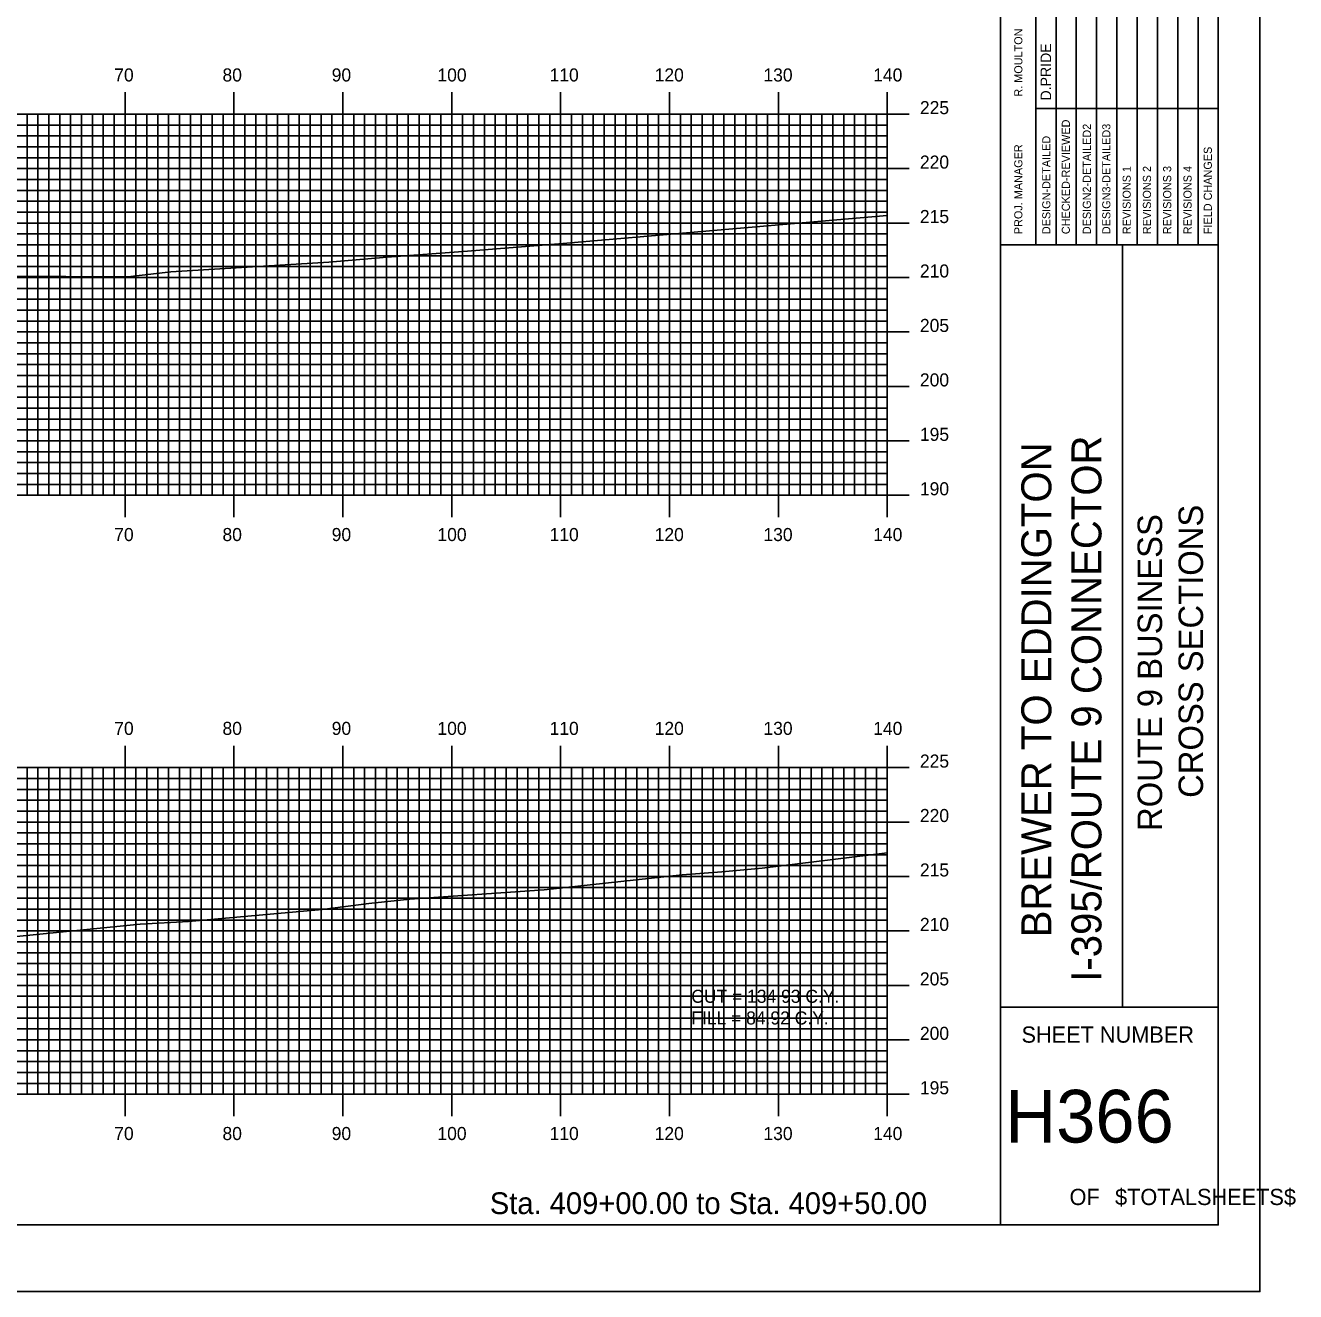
# Model space of a CAD drawing. Extents: x 852922 to 853266, y 364785 to 365005.
# Drawn here: x 853149.1 to 853265.7, y 364785.1 to 364901.4 of the extents above; entities that cross this region are included whole.
import ezdxf

# ---------------------------------------------------------------- set-up
doc = ezdxf.new("R2010")
doc.units = 0
for name, color, linetype in [('BORDER', 7, 'Continuous'), ('D_Text_Standard', 7, 'Continuous'), ('H_V ANNOTATION', 7, 'Continuous'), ('MAJOR', 7, 'Continuous'), ('MINOR', 7, 'Continuous'), ('PLOT BOUNDARY', 7, 'Continuous'), ('S_Roadway_Centerline', 7, 'Continuous')]:
    doc.layers.add(name, color=color, linetype=linetype)

msp = doc.modelspace()

# ---------------------------------------------------------------- linework, layer by layer
at = {"layer": 'BORDER'}
for p, q in [((853238.64, 364791.23), (853238.64, 365001.23)), ((853238.64, 364881.24), (853258.64, 364881.24)), ((853249.83, 364811.24), (853249.83, 364881.24)), ((853238.64, 364811.24), (853258.64, 364811.24))]:
    msp.add_line(p, q, dxfattribs=at)
msp.add_lwpolyline([(852938.64, 364791.23), (853258.64, 364791.23), (853258.64, 365001.23), (852938.64, 365001.23)], close=True, dxfattribs=at)
for points in [[(853243.74, 364881.24), (853243.74, 364916.24)], [(853245.6, 364916.24), (853245.6, 364881.24)], [(853247.47, 364881.24), (853247.47, 364916.24)], [(853249.33, 364881.24), (853249.33, 364916.24)], [(853251.19, 364881.24), (853251.19, 364916.24)], [(853253.06, 364881.24), (853253.06, 364916.24)], [(853254.92, 364881.24), (853254.92, 364916.24)], [(853256.78, 364881.24), (853256.78, 364916.24)], [(853241.88, 364881.24), (853241.88, 364914.83)], [(853241.87, 364893.74), (853258.64, 364893.74)]]:
    msp.add_lwpolyline(points, dxfattribs=at)
at = {"layer": 'MAJOR'}
for p, q in [((853158.24, 364895.24), (853158.24, 364893.23)), ((853168.24, 364895.24), (853168.24, 364893.23)), ((853178.24, 364895.24), (853178.24, 364893.23)), ((853188.24, 364895.24), (853188.24, 364893.23)), ((853198.24, 364895.24), (853198.24, 364893.23)), ((853208.24, 364895.24), (853208.24, 364893.23)), ((853218.24, 364895.24), (853218.24, 364893.23)), ((853228.24, 364895.24), (853228.24, 364893.23)), ((852948.24, 364893.23), (853228.24, 364893.23)), ((852948.24, 364893.23), (853228.24, 364893.23)), ((853158.24, 364858.23), (853158.24, 364893.23)), ((853168.24, 364858.23), (853168.24, 364893.23)), ((853178.24, 364858.23), (853178.24, 364893.23)), ((853188.24, 364858.23), (853188.24, 364893.23)), ((853198.24, 364858.23), (853198.24, 364893.23)), ((853208.24, 364858.23), (853208.24, 364893.23)), ((853218.24, 364858.23), (853218.24, 364893.23)), ((853230.25, 364893.23), (853226.24, 364893.23)), ((853228.24, 364858.23), (853228.24, 364893.23)), ((853228.24, 364858.23), (853228.24, 364893.23)), ((852948.24, 364888.23), (853228.24, 364888.23)), ((853230.25, 364888.23), (853226.24, 364888.23)), ((852948.24, 364883.23), (853228.24, 364883.23)), ((853230.25, 364883.23), (853226.24, 364883.23)), ((852948.24, 364878.23), (853228.24, 364878.23)), ((853230.25, 364878.23), (853226.24, 364878.23)), ((852948.24, 364873.23), (853228.24, 364873.23)), ((853230.25, 364873.23), (853226.24, 364873.23)), ((852948.24, 364868.23), (853228.24, 364868.23)), ((853230.25, 364868.23), (853226.24, 364868.23)), ((852948.24, 364863.23), (853228.24, 364863.23)), ((853230.25, 364863.23), (853226.24, 364863.23)), ((852948.24, 364858.23), (853228.24, 364858.23)), ((852948.24, 364858.23), (853228.24, 364858.23)), ((853158.24, 364856.23), (853158.24, 364858.23)), ((853168.24, 364856.23), (853168.24, 364858.23)), ((853178.24, 364856.23), (853178.24, 364858.23)), ((853188.24, 364856.23), (853188.24, 364858.23)), ((853198.24, 364856.23), (853198.24, 364858.23)), ((853208.24, 364856.23), (853208.24, 364858.23)), ((853218.24, 364856.23), (853218.24, 364858.23)), ((853230.25, 364858.23), (853226.24, 364858.23)), ((853228.24, 364856.23), (853228.24, 364858.23)), ((853158.24, 364835.24), (853158.24, 364833.23)), ((853168.24, 364835.24), (853168.24, 364833.23)), ((853178.24, 364835.24), (853178.24, 364833.23)), ((853188.24, 364835.24), (853188.24, 364833.23)), ((853198.24, 364835.24), (853198.24, 364833.23)), ((853208.24, 364835.24), (853208.24, 364833.23)), ((853218.24, 364835.24), (853218.24, 364833.23)), ((853228.24, 364835.24), (853228.24, 364833.23)), ((852948.24, 364833.23), (853228.24, 364833.23)), ((852948.24, 364833.23), (853228.24, 364833.23)), ((853158.24, 364803.23), (853158.24, 364833.23)), ((853168.24, 364803.23), (853168.24, 364833.23)), ((853178.24, 364803.23), (853178.24, 364833.23)), ((853188.24, 364803.23), (853188.24, 364833.23)), ((853198.24, 364803.23), (853198.24, 364833.23)), ((853208.24, 364803.23), (853208.24, 364833.23)), ((853218.24, 364803.23), (853218.24, 364833.23)), ((853230.25, 364833.23), (853226.24, 364833.23)), ((853228.24, 364803.23), (853228.24, 364833.23)), ((853228.24, 364803.23), (853228.24, 364833.23)), ((852948.24, 364828.23), (853228.24, 364828.23)), ((853230.25, 364828.23), (853226.24, 364828.23)), ((852948.24, 364823.23), (853228.24, 364823.23)), ((853230.25, 364823.23), (853226.24, 364823.23)), ((852948.24, 364818.23), (853228.24, 364818.23)), ((853230.25, 364818.23), (853226.24, 364818.23)), ((852948.24, 364813.23), (853228.24, 364813.23)), ((853230.25, 364813.23), (853226.24, 364813.23)), ((852948.24, 364808.23), (853228.24, 364808.23)), ((853230.25, 364808.23), (853226.24, 364808.23)), ((852948.24, 364803.23), (853228.24, 364803.23)), ((852948.24, 364803.23), (853228.24, 364803.23)), ((853158.24, 364801.23), (853158.24, 364803.23)), ((853168.24, 364801.23), (853168.24, 364803.23)), ((853178.24, 364801.23), (853178.24, 364803.23)), ((853188.24, 364801.23), (853188.24, 364803.23)), ((853198.24, 364801.23), (853198.24, 364803.23)), ((853208.24, 364801.23), (853208.24, 364803.23)), ((853218.24, 364801.23), (853218.24, 364803.23)), ((853230.25, 364803.23), (853226.24, 364803.23)), ((853228.24, 364801.23), (853228.24, 364803.23))]:
    msp.add_line(p, q, dxfattribs=at)
at = {"layer": 'MINOR'}
for p, q in [((853149.24, 364858.23), (853149.24, 364893.23)), ((853150.24, 364858.23), (853150.24, 364893.23)), ((853151.24, 364858.23), (853151.24, 364893.23)), ((853152.24, 364858.23), (853152.24, 364893.23)), ((853153.24, 364858.23), (853153.24, 364893.23)), ((853154.24, 364858.23), (853154.24, 364893.23)), ((853155.24, 364858.23), (853155.24, 364893.23)), ((853156.24, 364858.23), (853156.24, 364893.23)), ((853157.24, 364858.23), (853157.24, 364893.23)), ((853159.24, 364858.23), (853159.24, 364893.23)), ((853160.24, 364858.23), (853160.24, 364893.23)), ((853161.24, 364858.23), (853161.24, 364893.23)), ((853162.24, 364858.23), (853162.24, 364893.23)), ((853163.24, 364858.23), (853163.24, 364893.23)), ((853164.24, 364858.23), (853164.24, 364893.23)), ((853165.24, 364858.23), (853165.24, 364893.23)), ((853166.24, 364858.23), (853166.24, 364893.23)), ((853167.24, 364858.23), (853167.24, 364893.23)), ((853169.24, 364858.23), (853169.24, 364893.23)), ((853170.24, 364858.23), (853170.24, 364893.23)), ((853171.24, 364858.23), (853171.24, 364893.23)), ((853172.24, 364858.23), (853172.24, 364893.23)), ((853173.24, 364858.23), (853173.24, 364893.23)), ((853174.24, 364858.23), (853174.24, 364893.23)), ((853175.24, 364858.23), (853175.24, 364893.23)), ((853176.24, 364858.23), (853176.24, 364893.23)), ((853177.24, 364858.23), (853177.24, 364893.23)), ((853179.24, 364858.23), (853179.24, 364893.23)), ((853180.24, 364858.23), (853180.24, 364893.23)), ((853181.24, 364858.23), (853181.24, 364893.23)), ((853182.24, 364858.23), (853182.24, 364893.23)), ((853183.24, 364858.23), (853183.24, 364893.23)), ((853184.24, 364858.23), (853184.24, 364893.23)), ((853185.24, 364858.23), (853185.24, 364893.23)), ((853186.24, 364858.23), (853186.24, 364893.23)), ((853187.24, 364858.23), (853187.24, 364893.23)), ((853189.24, 364858.23), (853189.24, 364893.23)), ((853190.24, 364858.23), (853190.24, 364893.23)), ((853191.24, 364858.23), (853191.24, 364893.23)), ((853192.24, 364858.23), (853192.24, 364893.23)), ((853193.24, 364858.23), (853193.24, 364893.23)), ((853194.24, 364858.23), (853194.24, 364893.23)), ((853195.24, 364858.23), (853195.24, 364893.23)), ((853196.24, 364858.23), (853196.24, 364893.23)), ((853197.24, 364858.23), (853197.24, 364893.23)), ((853199.24, 364858.23), (853199.24, 364893.23)), ((853200.24, 364858.23), (853200.24, 364893.23)), ((853201.24, 364858.23), (853201.24, 364893.23)), ((853202.24, 364858.23), (853202.24, 364893.23)), ((853203.24, 364858.23), (853203.24, 364893.23)), ((853204.24, 364858.23), (853204.24, 364893.23)), ((853205.24, 364858.23), (853205.24, 364893.23)), ((853206.24, 364858.23), (853206.24, 364893.23)), ((853207.24, 364858.23), (853207.24, 364893.23)), ((853209.24, 364858.23), (853209.24, 364893.23)), ((853210.24, 364858.23), (853210.24, 364893.23)), ((853211.24, 364858.23), (853211.24, 364893.23)), ((853212.24, 364858.23), (853212.24, 364893.23)), ((853213.24, 364858.23), (853213.24, 364893.23)), ((853214.24, 364858.23), (853214.24, 364893.23)), ((853215.24, 364858.23), (853215.24, 364893.23)), ((853216.24, 364858.23), (853216.24, 364893.23)), ((853217.24, 364858.23), (853217.24, 364893.23)), ((853219.24, 364858.23), (853219.24, 364893.23)), ((853220.24, 364858.23), (853220.24, 364893.23)), ((853221.24, 364858.23), (853221.24, 364893.23)), ((853222.24, 364858.23), (853222.24, 364893.23)), ((853223.24, 364858.23), (853223.24, 364893.23)), ((853224.24, 364858.23), (853224.24, 364893.23)), ((853225.24, 364858.23), (853225.24, 364893.23)), ((853226.24, 364858.23), (853226.24, 364893.23)), ((853227.24, 364858.23), (853227.24, 364893.23)), ((852948.24, 364892.23), (853228.24, 364892.23)), ((853228.24, 364892.23), (853226.24, 364892.23)), ((852948.24, 364891.23), (853228.24, 364891.23)), ((853228.24, 364891.23), (853226.24, 364891.23)), ((852948.24, 364890.23), (853228.24, 364890.23)), ((852948.24, 364889.23), (853228.24, 364889.23)), ((853228.24, 364890.23), (853226.24, 364890.23)), ((853228.24, 364889.23), (853226.24, 364889.23)), ((852948.24, 364887.23), (853228.24, 364887.23)), ((853228.24, 364887.23), (853226.24, 364887.23)), ((852948.24, 364886.23), (853228.24, 364886.23)), ((853228.24, 364886.23), (853226.24, 364886.23)), ((852948.24, 364885.23), (853228.24, 364885.23)), ((853228.24, 364885.23), (853226.24, 364885.23)), ((852948.24, 364884.23), (853228.24, 364884.23)), ((853228.24, 364884.23), (853226.24, 364884.23)), ((852948.24, 364882.23), (853228.24, 364882.23)), ((853228.24, 364882.23), (853226.24, 364882.23)), ((852948.24, 364881.23), (853228.24, 364881.23)), ((853228.24, 364881.23), (853226.24, 364881.23)), ((852948.24, 364880.23), (853228.24, 364880.23)), ((853228.24, 364880.23), (853226.24, 364880.23)), ((852948.24, 364879.23), (853228.24, 364879.23)), ((853228.24, 364879.23), (853226.24, 364879.23)), ((852948.24, 364877.23), (853228.24, 364877.23)), ((853228.24, 364877.23), (853226.24, 364877.23)), ((852948.24, 364876.23), (853228.24, 364876.23)), ((852948.24, 364875.23), (853228.24, 364875.23)), ((853228.24, 364876.23), (853226.24, 364876.23)), ((853228.24, 364875.23), (853226.24, 364875.23)), ((852948.24, 364874.23), (853228.24, 364874.23)), ((853228.24, 364874.23), (853226.24, 364874.23)), ((852948.24, 364872.23), (853228.24, 364872.23)), ((853228.24, 364872.23), (853226.24, 364872.23)), ((852948.24, 364871.23), (853228.24, 364871.23)), ((853228.24, 364871.23), (853226.24, 364871.23)), ((852948.24, 364870.23), (853228.24, 364870.23)), ((853228.24, 364870.23), (853226.24, 364870.23)), ((852948.24, 364869.23), (853228.24, 364869.23)), ((853228.24, 364869.23), (853226.24, 364869.23)), ((852948.24, 364867.23), (853228.24, 364867.23)), ((853228.24, 364867.23), (853226.24, 364867.23)), ((852948.24, 364866.23), (853228.24, 364866.23)), ((853228.24, 364866.23), (853226.24, 364866.23)), ((852948.24, 364865.23), (853228.24, 364865.23)), ((853228.24, 364865.23), (853226.24, 364865.23)), ((852948.24, 364864.23), (853228.24, 364864.23)), ((853228.24, 364864.23), (853226.24, 364864.23)), ((852948.24, 364862.23), (853228.24, 364862.23)), ((852948.24, 364861.23), (853228.24, 364861.23)), ((853228.24, 364862.23), (853226.24, 364862.23)), ((853228.24, 364861.23), (853226.24, 364861.23)), ((852948.24, 364860.23), (853228.24, 364860.23)), ((853228.24, 364860.23), (853226.24, 364860.23)), ((852948.24, 364859.23), (853228.24, 364859.23)), ((853228.24, 364859.23), (853226.24, 364859.23)), ((853149.24, 364803.23), (853149.24, 364833.23)), ((853150.24, 364803.23), (853150.24, 364833.23)), ((853151.24, 364803.23), (853151.24, 364833.23)), ((853152.24, 364803.23), (853152.24, 364833.23)), ((853153.24, 364803.23), (853153.24, 364833.23)), ((853154.24, 364803.23), (853154.24, 364833.23)), ((853155.24, 364803.23), (853155.24, 364833.23)), ((853156.24, 364803.23), (853156.24, 364833.23)), ((853157.24, 364803.23), (853157.24, 364833.23)), ((853159.24, 364803.23), (853159.24, 364833.23)), ((853160.24, 364803.23), (853160.24, 364833.23)), ((853161.24, 364803.23), (853161.24, 364833.23)), ((853162.24, 364803.23), (853162.24, 364833.23)), ((853163.24, 364803.23), (853163.24, 364833.23)), ((853164.24, 364803.23), (853164.24, 364833.23)), ((853165.24, 364803.23), (853165.24, 364833.23)), ((853166.24, 364803.23), (853166.24, 364833.23)), ((853167.24, 364803.23), (853167.24, 364833.23)), ((853169.24, 364803.23), (853169.24, 364833.23)), ((853170.24, 364803.23), (853170.24, 364833.23)), ((853171.24, 364803.23), (853171.24, 364833.23)), ((853172.24, 364803.23), (853172.24, 364833.23)), ((853173.24, 364803.23), (853173.24, 364833.23)), ((853174.24, 364803.23), (853174.24, 364833.23)), ((853175.24, 364803.23), (853175.24, 364833.23)), ((853176.24, 364803.23), (853176.24, 364833.23)), ((853177.24, 364803.23), (853177.24, 364833.23)), ((853179.24, 364803.23), (853179.24, 364833.23)), ((853180.24, 364803.23), (853180.24, 364833.23)), ((853181.24, 364803.23), (853181.24, 364833.23)), ((853182.24, 364803.23), (853182.24, 364833.23)), ((853183.24, 364803.23), (853183.24, 364833.23)), ((853184.24, 364803.23), (853184.24, 364833.23)), ((853185.24, 364803.23), (853185.24, 364833.23)), ((853186.24, 364803.23), (853186.24, 364833.23)), ((853187.24, 364803.23), (853187.24, 364833.23)), ((853189.24, 364803.23), (853189.24, 364833.23)), ((853190.24, 364803.23), (853190.24, 364833.23)), ((853191.24, 364803.23), (853191.24, 364833.23)), ((853192.24, 364803.23), (853192.24, 364833.23)), ((853193.24, 364803.23), (853193.24, 364833.23)), ((853194.24, 364803.23), (853194.24, 364833.23)), ((853195.24, 364803.23), (853195.24, 364833.23)), ((853196.24, 364803.23), (853196.24, 364833.23)), ((853197.24, 364803.23), (853197.24, 364833.23)), ((853199.24, 364803.23), (853199.24, 364833.23)), ((853200.24, 364803.23), (853200.24, 364833.23)), ((853201.24, 364803.23), (853201.24, 364833.23)), ((853202.24, 364803.23), (853202.24, 364833.23)), ((853203.24, 364803.23), (853203.24, 364833.23)), ((853204.24, 364803.23), (853204.24, 364833.23)), ((853205.24, 364803.23), (853205.24, 364833.23)), ((853206.24, 364803.23), (853206.24, 364833.23)), ((853207.24, 364803.23), (853207.24, 364833.23)), ((853209.24, 364803.23), (853209.24, 364833.23)), ((853210.24, 364803.23), (853210.24, 364833.23)), ((853211.24, 364803.23), (853211.24, 364833.23)), ((853212.24, 364803.23), (853212.24, 364833.23)), ((853213.24, 364803.23), (853213.24, 364833.23)), ((853214.24, 364803.23), (853214.24, 364833.23)), ((853215.24, 364803.23), (853215.24, 364833.23)), ((853216.24, 364803.23), (853216.24, 364833.23)), ((853217.24, 364803.23), (853217.24, 364833.23)), ((853219.24, 364803.23), (853219.24, 364833.23)), ((853220.24, 364803.23), (853220.24, 364833.23)), ((853221.24, 364803.23), (853221.24, 364833.23)), ((853222.24, 364803.23), (853222.24, 364833.23)), ((853223.24, 364803.23), (853223.24, 364833.23)), ((853224.24, 364803.23), (853224.24, 364833.23)), ((853225.24, 364803.23), (853225.24, 364833.23)), ((853226.24, 364803.23), (853226.24, 364833.23)), ((853227.24, 364803.23), (853227.24, 364833.23)), ((852948.24, 364832.23), (853228.24, 364832.23)), ((853228.24, 364832.23), (853226.24, 364832.23)), ((852948.24, 364831.23), (853228.24, 364831.23)), ((853228.24, 364831.23), (853226.24, 364831.23)), ((852948.24, 364830.23), (853228.24, 364830.23)), ((853228.24, 364830.23), (853226.24, 364830.23)), ((852948.24, 364829.23), (853228.24, 364829.23)), ((853228.24, 364829.23), (853226.24, 364829.23)), ((852948.24, 364827.23), (853228.24, 364827.23)), ((852948.24, 364826.23), (853228.24, 364826.23)), ((853228.24, 364827.23), (853226.24, 364827.23)), ((853228.24, 364826.23), (853226.24, 364826.23)), ((852948.24, 364825.23), (853228.24, 364825.23)), ((853228.24, 364825.23), (853226.24, 364825.23)), ((852948.24, 364824.23), (853228.24, 364824.23)), ((853228.24, 364824.23), (853226.24, 364824.23)), ((852948.24, 364822.23), (853228.24, 364822.23)), ((853228.24, 364822.23), (853226.24, 364822.23)), ((852948.24, 364821.23), (853228.24, 364821.23)), ((853228.24, 364821.23), (853226.24, 364821.23)), ((852948.24, 364820.23), (853228.24, 364820.23)), ((852948.24, 364819.23), (853228.24, 364819.23)), ((853228.24, 364820.23), (853226.24, 364820.23)), ((853228.24, 364819.23), (853226.24, 364819.23)), ((852948.24, 364817.23), (853228.24, 364817.23)), ((853228.24, 364817.23), (853226.24, 364817.23)), ((852948.24, 364816.23), (853228.24, 364816.23)), ((853228.24, 364816.23), (853226.24, 364816.23)), ((852948.24, 364815.23), (853228.24, 364815.23)), ((853228.24, 364815.23), (853226.24, 364815.23)), ((852948.24, 364814.23), (853228.24, 364814.23)), ((853228.24, 364814.23), (853226.24, 364814.23)), ((852948.24, 364812.23), (853228.24, 364812.23)), ((853228.24, 364812.23), (853226.24, 364812.23)), ((852948.24, 364811.23), (853228.24, 364811.23)), ((853228.24, 364811.23), (853226.24, 364811.23)), ((852948.24, 364810.23), (853228.24, 364810.23)), ((853228.24, 364810.23), (853226.24, 364810.23)), ((852948.24, 364809.23), (853228.24, 364809.23)), ((853228.24, 364809.23), (853226.24, 364809.23)), ((852948.24, 364807.23), (853228.24, 364807.23)), ((853228.24, 364807.23), (853226.24, 364807.23)), ((852948.24, 364806.23), (853228.24, 364806.23)), ((852948.24, 364805.23), (853228.24, 364805.23)), ((853228.24, 364806.23), (853226.24, 364806.23)), ((853228.24, 364805.23), (853226.24, 364805.23)), ((852948.24, 364804.23), (853228.24, 364804.23)), ((853228.24, 364804.23), (853226.24, 364804.23))]:
    msp.add_line(p, q, dxfattribs=at)
at = {"layer": 'PLOT BOUNDARY'}
msp.add_lwpolyline([(852922.46, 364785.11), (853262.46, 364785.11), (853262.46, 365005.11), (852922.46, 365005.11)], close=True, dxfattribs=at)
at = {"layer": 'S_Roadway_Centerline'}
for points in [[(853141.36, 364878.39), (853158.49, 364878.3), (853162.45, 364878.75), (853176.97, 364879.65), (853182.32, 364880.09), (853189.7, 364880.66), (853198.44, 364881.36), (853228.24, 364883.92)], [(853147.96, 364817.69), (853159.64, 364818.86), (853164.08, 364819.1), (853176.33, 364820.2), (853180.64, 364820.76), (853184.41, 364821.14), (853196.72, 364822.01), (853209.41, 364823.39), (853213.06, 364823.67), (853216.74, 364823.99), (853228.24, 364825.39)]]:
    msp.add_lwpolyline(points, dxfattribs=at)

# ---------------------------------------------------------------- texts
at = {"layer": 'BORDER'}
for s, height, p in [('R. MOULTON', 0.745, (853240.65, 364894.84)), ('D.PRIDE', 0.969, (853243.29, 364894.48)), ('CHECKED-REVIEWED', 0.7455, (853245.01, 364882.21)), ('DESIGN2-DETAILED2', 0.7455, (853246.94, 364882.21)), ('DESIGN3-DETAILED3', 0.7455, (853248.73, 364882.21)), ('PROJ. MANAGER', 0.7455, (853240.65, 364882.21)), ('DESIGN-DETAILED', 0.7455, (853243.22, 364882.21)), ('FIELD CHANGES', 0.7455, (853258.05, 364882.21)), ('REVISIONS 1', 0.7455, (853250.6, 364882.21)), ('REVISIONS 2', 0.7455, (853252.46, 364882.21)), ('REVISIONS 3', 0.7455, (853254.32, 364882.21)), ('REVISIONS 4', 0.7455, (853256.19, 364882.21)), ('I-395/ROUTE 9 CONNECTOR', 2.7557, (853247.91, 364813.56)), ('BREWER TO EDDINGTON', 2.7557, (853243.31, 364817.64)), ('CROSS SECTIONS', 2.25, (853257.24, 364830.45)), ('ROUTE 9 BUSINESS', 2.25, (853253.48, 364827.41))]:
    msp.add_text(s, height=height, rotation=90, dxfattribs=at).set_placement(p)
for s, height, p in [('SHEET NUMBER', 1.4905, (853240.57, 364807.97)), ('H366', 4.839, (853239.08, 364798.8)), ('OF', 1.491, (853244.98, 364793.06)), ('$TOTALSHEETS$', 1.4905, (853249.16, 364793.06))]:
    msp.add_text(s, height=height, dxfattribs=at).set_placement(p)
at = {"layer": 'D_Text_Standard'}
for s, p in [('CUT = 134.93 C.Y.', (853210.24, 364811.63)), ('FILL = 84.92 C.Y.', (853210.24, 364809.64))]:
    msp.add_text(s, height=1.2, dxfattribs=at).set_placement(p)
at = {"layer": 'H_V ANNOTATION'}
for s, height, p in [('70', 1.2, (853157.25, 364896.23)), ('80', 1.2, (853167.19, 364896.23)), ('90', 1.2, (853177.22, 364896.23)), ('100', 1.2, (853186.93, 364896.23)), ('110', 1.2, (853197.23, 364896.23)), ('120', 1.2, (853206.88, 364896.23)), ('130', 1.2, (853216.87, 364896.23)), ('140', 1.2, (853226.95, 364896.23)), ('225', 1.2, (853231.24, 364893.23)), ('220', 1.2, (853231.24, 364888.23)), ('215', 1.2, (853231.24, 364883.23)), ('210', 1.2, (853231.24, 364878.23)), ('205', 1.2, (853231.24, 364873.23)), ('200', 1.2, (853231.24, 364868.23)), ('195', 1.2, (853231.24, 364863.23)), ('190', 1.2, (853231.24, 364858.23)), ('70', 1.2, (853157.25, 364854.03)), ('80', 1.2, (853167.19, 364854.03)), ('90', 1.2, (853177.22, 364854.03)), ('100', 1.2, (853186.93, 364854.03)), ('110', 1.2, (853197.23, 364854.03)), ('120', 1.2, (853206.88, 364854.03)), ('130', 1.2, (853216.87, 364854.03)), ('140', 1.2, (853226.95, 364854.03)), ('70', 1.2, (853157.25, 364836.23)), ('80', 1.2, (853167.19, 364836.23)), ('90', 1.2, (853177.22, 364836.23)), ('100', 1.2, (853186.93, 364836.23)), ('110', 1.2, (853197.23, 364836.23)), ('120', 1.2, (853206.88, 364836.23)), ('130', 1.2, (853216.87, 364836.23)), ('140', 1.2, (853226.95, 364836.23)), ('225', 1.2, (853231.24, 364833.23)), ('220', 1.2, (853231.24, 364828.23)), ('215', 1.2, (853231.24, 364823.23)), ('210', 1.2, (853231.24, 364818.23)), ('205', 1.2, (853231.24, 364813.23)), ('200', 1.2, (853231.24, 364808.23)), ('195', 1.2, (853231.24, 364803.23)), ('70', 1.2, (853157.25, 364799.03)), ('80', 1.2, (853167.19, 364799.03)), ('90', 1.2, (853177.22, 364799.03)), ('100', 1.2, (853186.93, 364799.03)), ('110', 1.2, (853197.23, 364799.03)), ('120', 1.2, (853206.88, 364799.03)), ('130', 1.2, (853216.87, 364799.03)), ('140', 1.2, (853226.95, 364799.03)), ('Sta. 409+00.00 to Sta. 409+50.00', 2.0004, (853191.74, 364792.23))]:
    msp.add_text(s, height=height, dxfattribs=at).set_placement(p)

doc.saveas('drawing.dxf')
